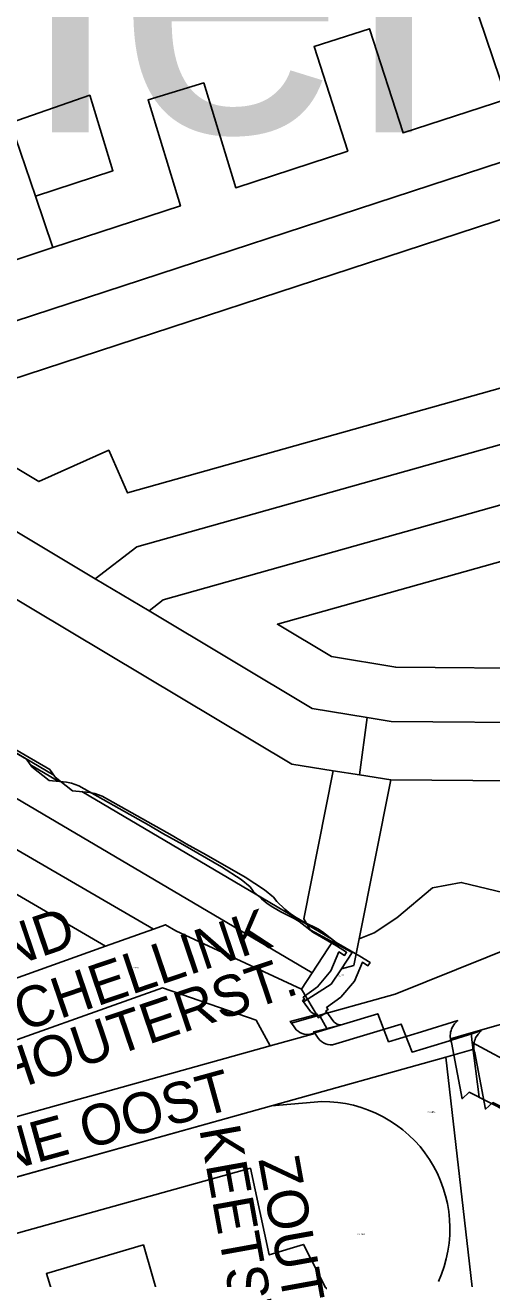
# Model space of a CAD drawing. Extents: x 14356 to 207184, y 3423 to 537581.
# Drawn here: x 133359.6 to 133479.8, y 517028.5 to 517351.4 of the extents above; entities that cross this region are included whole.
import ezdxf

# ---------------------------------------------------------------- set-up
doc = ezdxf.new("R2010")
doc.units = 0
for name, color, linetype in [('(THEMA) WIJK (VLAK)', 7, 'Continuous'), ('FRANK', 7, 'Continuous'), ('GEOCAD IKB VLAK TEKST CLASSIFICATIE', 7, 'Continuous'), ('KADER-35', 7, 'Continuous'), ('PLATTEGROND ACHTERGROND BEBOUW', 7, 'Continuous'), ('PLATTEGROND BEBOUWING', 7, 'Continuous'), ('PLATTEGROND ERFTOEGANGSWEG', 7, 'Continuous'), ('PLATTEGROND GEB ONTSL WEG C', 7, 'Continuous'), ('PLATTEGROND GEB ONTSL WEG E', 7, 'Continuous'), ('PLATTEGROND HULPLIJN', 7, 'Continuous'), ('PLATTEGROND LIJN', 7, 'Continuous'), ('PLATTEGROND NAAM ERFTOEGANGSWEG', 7, 'Continuous'), ('PLATTEGROND NAAM GEB ONTSL WEG E', 7, 'Continuous'), ('PLATTEGROND OPENBAAR GROEN', 7, 'Continuous'), ('PLATTEGROND VOET FIETSPAD', 7, 'Continuous'), ('PLATTEGROND WATER', 7, 'Continuous')]:
    doc.layers.add(name, color=color, linetype=linetype)

msp = doc.modelspace()

# ---------------------------------------------------------------- linework, layer by layer
at = {"layer": '(THEMA) WIJK (VLAK)'}
for points in [[(133337.82, 517175.95), (133365.97, 517159.67), (133367.32, 517157.73), (133371.82, 517154.22), (133376.25, 517153.77), (133377.53, 517153.49), (133379.43, 517152.79), (133397.48, 517142.72), (133401.09, 517140.55), (133406.25, 517137.72), (133416.24, 517131.99), (133421.27, 517128.71), (133423.58, 517126.79), (133424.37, 517125.68), (133426.47, 517123.67), (133427.95, 517122.53), (133429.4, 517121.57), (133431.48, 517120.36), (133434.95, 517118.64), (133436.19, 517117.86), (133439.68, 517115.14), (133445.81, 517111.59), (133448.42, 517109.97), (133447.88, 517109.15), (133446.44, 517110.05), (133444.37, 517105.21), (133440.89, 517101.01), (133437.24, 517098.35), (133437.59, 517097.87), (133437.07, 517097.51), (133439.13, 517094.69)], [(133439.13, 517094.69), (133437.07, 517097.51), (133437.59, 517097.87), (133437.24, 517098.35), (133440.89, 517101.01), (133444.37, 517105.21), (133446.44, 517110.05), (133447.88, 517109.15), (133448.42, 517109.97), (133445.81, 517111.59), (133439.68, 517115.14), (133436.19, 517117.86), (133434.95, 517118.64), (133431.48, 517120.36), (133429.4, 517121.57), (133427.95, 517122.53), (133426.47, 517123.67), (133424.37, 517125.68), (133423.58, 517126.79), (133421.27, 517128.71), (133416.24, 517131.99), (133406.25, 517137.72), (133401.09, 517140.55), (133397.48, 517142.72), (133379.43, 517152.79), (133377.53, 517153.49), (133376.25, 517153.77), (133371.82, 517154.22), (133367.32, 517157.73), (133365.97, 517159.67), (133337.82, 517175.95)], [(133441.02, 517093.96), (133433.9, 517092.15), (133434.71, 517090.97)], [(133434.71, 517090.97), (133433.9, 517092.15), (133441.02, 517093.96)], [(133438.73, 517088.76), (133456.45, 517094.12), (133459.22, 517086.92), (133467.73, 517089.45), (133477.02, 517092.34), (133476.22, 517091.5), (133475.6, 517090.54)], [(133475.6, 517090.54), (133476.22, 517091.5), (133477.02, 517092.34), (133467.73, 517089.45), (133459.22, 517086.92), (133456.45, 517094.12), (133438.73, 517088.76)], [(133475.18, 517087.35), (133475.4, 517086.67), (133478.13, 517072.21), (133479.99, 517073.92), (133494.79, 517066.39), (133507.34, 517060.27), (133512.87, 517057.42), (133608.91, 517004.69)], [(133608.91, 517004.69), (133512.87, 517057.42), (133507.34, 517060.27), (133494.79, 517066.39), (133479.99, 517073.92), (133478.13, 517072.21), (133475.4, 517086.67), (133475.18, 517087.35)]]:
    msp.add_lwpolyline(points, dxfattribs=at)
for centre, radius, start, end in [((133440.66, 517095.86), 1.93, 217.3612, 280.6329), ((133440.66, 517095.86), 1.93, 217.3612, 280.6329), ((133438.52, 517093.13), 4.37, 209.5213, 272.7871), ((133438.52, 517093.13), 4.37, 209.5213, 272.7871), ((133480.3, 517088.31), 5.2, 154.5796, 190.5868), ((133480.3, 517088.31), 5.2, 154.5796, 190.5868)]:
    msp.add_arc(centre, radius, start, end, dxfattribs=at)
at = {"layer": 'FRANK'}
for points in [[(133337.82, 517175.95), (133365.97, 517159.67), (133367.32, 517157.73), (133371.82, 517154.22), (133376.25, 517153.77), (133377.53, 517153.49), (133379.43, 517152.79), (133397.48, 517142.72), (133401.09, 517140.55), (133406.25, 517137.72), (133416.24, 517131.99), (133421.27, 517128.71), (133423.58, 517126.79), (133424.37, 517125.68), (133426.47, 517123.67), (133427.95, 517122.53), (133429.4, 517121.57), (133431.48, 517120.36), (133434.95, 517118.64), (133436.19, 517117.86), (133439.68, 517115.14), (133445.81, 517111.59), (133448.42, 517109.97), (133447.88, 517109.15), (133446.44, 517110.05), (133444.37, 517105.21), (133440.89, 517101.01), (133437.24, 517098.35), (133437.59, 517097.87), (133437.07, 517097.51), (133439.13, 517094.69)], [(133441.02, 517093.96), (133433.9, 517092.15), (133434.71, 517090.97)], [(133438.73, 517088.76), (133456.45, 517094.12), (133459.22, 517086.92), (133467.73, 517089.45), (133477.02, 517092.34), (133476.22, 517091.5), (133475.6, 517090.54)], [(133475.18, 517087.35), (133475.4, 517086.67), (133478.13, 517072.21), (133479.99, 517073.92), (133494.79, 517066.39), (133507.34, 517060.27), (133512.87, 517057.42), (133608.91, 517004.69)]]:
    msp.add_lwpolyline(points, dxfattribs=at)
for centre, radius, start, end in [((133440.66, 517095.86), 1.93, 217.3612, 280.6329), ((133438.52, 517093.13), 4.37, 209.5213, 272.7871), ((133480.3, 517088.31), 5.2, 154.5796, 190.5868)]:
    msp.add_arc(centre, radius, start, end, dxfattribs=at)
at = {"layer": 'KADER-35'}
for points in [[(133433.09, 517097.35), (133431.04, 517100.18), (133431.55, 517100.53), (133431.21, 517101.01), (133434.86, 517103.67), (133438.34, 517107.87), (133440.41, 517112.71), (133441.85, 517111.81), (133442.39, 517112.63), (133439.78, 517114.26), (133433.65, 517117.81), (133430.16, 517120.52), (133428.91, 517121.3), (133425.44, 517123.03), (133423.37, 517124.23), (133421.92, 517125.19), (133420.44, 517126.34), (133418.34, 517128.34), (133417.55, 517129.45), (133415.24, 517131.37), (133410.2, 517134.65), (133400.22, 517140.38), (133395.06, 517143.21), (133391.44, 517145.38), (133373.39, 517155.45), (133371.5, 517156.15), (133370.22, 517156.43), (133365.79, 517156.88), (133361.29, 517160.39), (133359.93, 517162.34), (133331.78, 517178.61)], [(133428.68, 517093.64), (133427.87, 517094.82), (133434.99, 517096.63)], [(133469.57, 517093.2), (133470.18, 517094.16), (133470.99, 517095), (133461.69, 517092.11), (133453.19, 517089.58), (133450.41, 517096.79), (133432.7, 517091.42)], [(133602.88, 517007.36), (133506.84, 517060.08), (133501.31, 517062.93), (133488.76, 517069.05), (133473.96, 517076.58), (133472.1, 517074.87), (133469.37, 517089.33), (133469.15, 517090.01)]]:
    msp.add_lwpolyline(points, dxfattribs=at)
for centre, radius, start, end in [((133434.63, 517098.52), 1.93, 217.3612, 280.6329), ((133432.48, 517095.79), 4.37, 209.5213, 272.7871), ((133474.26, 517090.97), 5.2, 154.5796, 190.5868)]:
    msp.add_arc(centre, radius, start, end, dxfattribs=at)
at = {"layer": 'PLATTEGROND ACHTERGROND BEBOUW'}
msp.add_line((133362.23, 517307.34), (133355.82, 517326.25), dxfattribs=at)
for points in [[(133355.82, 517326.25), (133376.25, 517333.3), (133382.18, 517313.87), (133362.23, 517307.34)], [(133499.9, 517289.83), (133486.63, 517285.39), (133495.01, 517261.55), (133385.99, 517230.9), (133381.14, 517241.88), (133363.11, 517233.84), (133332.24, 517252.3), (133494.45, 517305.34)], [(133533.47, 517194.41), (133522.02, 517191.14), (133495.48, 517185.71), (133455.02, 517186.02), (133438.47, 517188.78), (133424.58, 517197.08), (133509.31, 517220.91), (133516.02, 517201.81), (133529.31, 517206.23)], [(133346.62, 517002.28), (133335.32, 517034.07), (133417.59, 517056.98), (133422.45, 517034.68), (133431.24, 517037.38), (133436.97, 517026.27), (133444.97, 517019.88), (133449.99, 517019.42), (133450.34, 517011.6)], [(133397.06, 517013.08), (133390.07, 517037.24), (133365.06, 517029.88), (133371.9, 517007.7)]]:
    msp.add_lwpolyline(points, dxfattribs=at)
at = {"layer": 'PLATTEGROND BEBOUWING'}
for p, q in [((133463.57, 517391.43), (133483.63, 517332.32)), ((133298.68, 517256.05), (133489.8, 517318.55)), ((133366.72, 517294.08), (133362.23, 517307.34)), ((133377.67, 517208.82), (133298.68, 517256.05)), ((133432.94, 517118.36), (133432.96, 517118.39)), ((133433.53, 517107.34), (133438.97, 517115.7)), ((133430.8, 517103.14), (133433.53, 517107.34)), ((133437.32, 517097.16), (133435.61, 517096.07)), ((133422.66, 517088.5), (133310.74, 517057.32)), ((133317.11, 517043.53), (133423.04, 517073.03))]:
    msp.add_line(p, q, dxfattribs=at)
for points in [[(133483.63, 517332.32), (133456.94, 517323.59), (133448.26, 517350.45), (133433.99, 517345.84), (133442.68, 517318.92), (133413.84, 517309.49), (133405.6, 517336.49), (133391.25, 517332.11), (133399.58, 517304.83), (133366.72, 517294.08)], [(133362.23, 517307.34), (133382.18, 517313.87), (133376.25, 517333.3), (133355.82, 517326.25)], [(133494.45, 517305.34), (133332.24, 517252.3), (133363.11, 517233.84), (133381.14, 517241.88), (133385.99, 517230.9), (133495.01, 517261.55), (133486.63, 517285.39), (133499.9, 517289.83)], [(133513.17, 517252.12), (133388.34, 517217.02), (133377.67, 517208.82)], [(133391.51, 517200.54), (133395.18, 517203.36), (133518.16, 517237.94)], [(133529.31, 517206.23), (133516.02, 517201.81), (133509.31, 517220.91), (133424.58, 517197.08), (133438.47, 517188.78), (133455.02, 517186.02), (133495.48, 517185.71), (133522.02, 517191.14), (133533.47, 517194.41)], [(133447.69, 517173.05), (133433.55, 517175.41), (133391.51, 517200.54)], [(133538.12, 517181.18), (133525.36, 517177.53), (133496.85, 517171.7), (133453.81, 517172.03), (133447.69, 517173.05)], [(133265.86, 517119.46), (133341.04, 517136.98), (133380.33, 517114.2)], [(133432.96, 517118.39), (133443.78, 517112.54), (133441.03, 517108.34)], [(133380.33, 517114.2), (133338.81, 517099.37), (133343.85, 517085.24), (133394.94, 517103.49), (133419.05, 517095.1), (133422.66, 517088.5)], [(133441.03, 517108.34), (133438.44, 517104.41), (133431.29, 517099.82)], [(133435.61, 517096.07), (133435.11, 517095.74), (133430.8, 517103.14)], [(133423.04, 517073.03), (133435.98, 517074.16), (133438.03, 517074.11), (133440.08, 517073.94), (133442.11, 517073.64), (133444.12, 517073.21), (133446.1, 517072.66), (133448.04, 517071.98), (133449.93, 517071.18), (133451.77, 517070.26), (133453.54, 517069.24), (133455.25, 517068.1), (133456.89, 517066.85), (133458.44, 517065.51), (133459.91, 517064.07), (133461.28, 517062.55), (133462.55, 517060.93), (133463.73, 517059.25), (133464.79, 517057.49), (133465.74, 517055.67), (133466.57, 517053.79), (133467.28, 517051.87), (133467.88, 517049.9), (133468.34, 517047.9), (133468.68, 517045.87), (133468.9, 517043.83), (133468.98, 517041.78), (133468.93, 517039.73), (133468.76, 517037.68), (133468.46, 517035.65), (133468.03, 517033.64), (133467.48, 517031.66), (133466.8, 517029.72), (133466, 517027.83)], [(133450.34, 517011.6), (133449.99, 517019.42), (133444.97, 517019.88), (133436.97, 517026.27), (133431.24, 517037.38), (133422.45, 517034.68), (133417.59, 517056.98), (133335.32, 517034.07), (133346.62, 517002.28)], [(133371.9, 517007.7), (133365.06, 517029.88), (133390.07, 517037.24), (133397.06, 517013.08)]]:
    msp.add_lwpolyline(points, dxfattribs=at)
at = {"layer": 'PLATTEGROND ERFTOEGANGSWEG'}
for p, q in [((133483.63, 517332.32), (133463.57, 517391.43)), ((133355.82, 517326.25), (133362.23, 517307.34)), ((133489.8, 517318.55), (133298.68, 517256.05)), ((133362.23, 517307.34), (133366.72, 517294.08)), ((133352.46, 517289.42), (133366.72, 517294.08)), ((133366.72, 517294.08), (133352.46, 517289.42)), ((133391.51, 517200.54), (133377.67, 517208.82)), ((133380.33, 517114.2), (133392.66, 517118.6)), ((133431.46, 517095.29), (133428.17, 517094.38)), ((133431.25, 517095.68), (133431.46, 517095.29)), ((133435.61, 517096.07), (133437.28, 517093.01)), ((133434.2, 517091.71), (133422.66, 517088.5)), ((133469.11, 517090.31), (133474.42, 517091.84)), ((133474.42, 517091.84), (133474.73, 517089.41)), ((133467.89, 517085.56), (133475.14, 517087.65)), ((133476.54, 517075.27), (133474.73, 517089.41)), ((133474.73, 517089.41), (133512.31, 517068.89)), ((133474.73, 517089.41), (133476.54, 517075.27)), ((133475.96, 517015.81), (133467.89, 517085.56))]:
    msp.add_line(p, q, dxfattribs=at)
for points in [[(133366.72, 517294.08), (133399.58, 517304.83), (133391.25, 517332.11), (133405.6, 517336.49), (133413.84, 517309.49), (133442.68, 517318.92), (133433.99, 517345.84), (133448.26, 517350.45), (133456.94, 517323.59), (133483.63, 517332.32)], [(133377.67, 517208.82), (133388.34, 517217.02), (133513.17, 517252.12)], [(133518.16, 517237.94), (133395.18, 517203.36), (133391.51, 517200.54)], [(133392.66, 517118.6), (133395.74, 517119.7), (133398.38, 517118.17), (133430.8, 517103.14)], [(133422.66, 517088.5), (133419.05, 517095.1), (133394.94, 517103.49), (133343.85, 517085.24), (133338.81, 517099.37), (133380.33, 517114.2)], [(133430.8, 517103.14), (133435.11, 517095.74), (133435.61, 517096.07)]]:
    msp.add_lwpolyline(points, dxfattribs=at)
at = {"layer": 'PLATTEGROND GEB ONTSL WEG C'}
for p, q in [((133298.68, 517256.05), (133377.67, 517208.82)), ((133377.67, 517208.82), (133391.51, 517200.54)), ((133447.69, 517173.05), (133445.7, 517158.27)), ((133445.7, 517158.27), (133447.69, 517173.05)), ((133445.7, 517158.27), (133438.94, 517159.3)), ((133453.78, 517157.03), (133445.7, 517158.27)), ((133485.46, 517156.79), (133453.78, 517157.03))]:
    msp.add_line(p, q, dxfattribs=at)
for points in [[(133438.94, 517159.3), (133428.29, 517161.08), (133170.78, 517315.04), (133147.96, 517361.08)], [(133391.51, 517200.54), (133433.55, 517175.41), (133447.69, 517173.05)], [(133447.69, 517173.05), (133453.81, 517172.03), (133496.85, 517171.7), (133525.36, 517177.53), (133538.12, 517181.18)]]:
    msp.add_lwpolyline(points, dxfattribs=at)
at = {"layer": 'PLATTEGROND GEB ONTSL WEG E'}
for p, q in [((133428.17, 517094.38), (133431.46, 517095.29)), ((133422.66, 517088.5), (133434.2, 517091.71)), ((133474.42, 517091.84), (133469.11, 517090.31)), ((133310.74, 517057.32), (133422.66, 517088.5)), ((133475.14, 517087.65), (133467.89, 517085.56)), ((133467.89, 517085.56), (133423.04, 517073.03)), ((133423.04, 517073.03), (133317.11, 517043.53))]:
    msp.add_line(p, q, dxfattribs=at)
for points in [[(133431.46, 517095.29), (133454.9, 517101.82), (133486.43, 517114.52)], [(133494.57, 517098.24), (133488.96, 517096.02), (133474.42, 517091.84)]]:
    msp.add_lwpolyline(points, dxfattribs=at)
at = {"layer": 'PLATTEGROND HULPLIJN'}
for p, q in [((133366.72, 517294.08), (133352.46, 517289.42)), ((133377.67, 517208.82), (133391.51, 517200.54)), ((133445.7, 517158.27), (133447.69, 517173.05)), ((133445.7, 517158.27), (133438.94, 517159.3)), ((133453.78, 517157.03), (133445.7, 517158.27)), ((133380.33, 517114.2), (133392.66, 517118.6)), ((133428.17, 517094.38), (133431.46, 517095.29)), ((133422.66, 517088.5), (133434.2, 517091.71)), ((133469.11, 517090.31), (133474.42, 517091.84)), ((133467.89, 517085.56), (133475.14, 517087.65)), ((133476.54, 517075.27), (133474.73, 517089.41))]:
    msp.add_line(p, q, dxfattribs=at)
at = {"layer": 'PLATTEGROND LIJN'}
for p, q in [((133483.63, 517332.32), (133463.57, 517391.43)), ((133355.82, 517326.25), (133362.23, 517307.34)), ((133489.8, 517318.55), (133298.68, 517256.05)), ((133362.23, 517307.34), (133366.72, 517294.08)), ((133298.68, 517256.05), (133377.67, 517208.82)), ((133433.53, 517107.34), (133212.4, 517237.59)), ((133366.99, 517158.21), (133278.56, 517210.38)), ((133368.13, 517156.64), (133360.95, 517160.87)), ((133445.59, 517116.1), (133453.78, 517157.03)), ((133453.78, 517157.03), (133485.46, 517156.79)), ((133438.74, 517115.88), (133374.16, 517153.98)), ((133432.96, 517118.39), (133432.71, 517118.54)), ((133432.96, 517118.39), (133432.94, 517118.36)), ((133438.97, 517115.7), (133433.53, 517107.34)), ((133433.53, 517107.34), (133430.8, 517103.14)), ((133435.61, 517096.07), (133437.32, 517097.16)), ((133431.46, 517095.29), (133431.25, 517095.68)), ((133437.28, 517093.01), (133435.61, 517096.07)), ((133474.73, 517089.41), (133474.42, 517091.84)), ((133310.74, 517057.32), (133422.66, 517088.5)), ((133512.31, 517068.89), (133474.73, 517089.41)), ((133467.89, 517085.56), (133423.04, 517073.03)), ((133467.89, 517085.56), (133475.96, 517015.81)), ((133423.04, 517073.03), (133317.11, 517043.53))]:
    msp.add_line(p, q, dxfattribs=at)
for points in [[(133438.94, 517159.3), (133428.29, 517161.08), (133170.78, 517315.04), (133147.96, 517361.08)], [(133366.72, 517294.08), (133399.58, 517304.83), (133391.25, 517332.11), (133405.6, 517336.49), (133413.84, 517309.49), (133442.68, 517318.92), (133433.99, 517345.84), (133448.26, 517350.45), (133456.94, 517323.59), (133483.63, 517332.32)], [(133355.82, 517326.25), (133376.25, 517333.3), (133382.18, 517313.87), (133362.23, 517307.34)], [(133494.45, 517305.34), (133332.24, 517252.3), (133363.11, 517233.84), (133381.14, 517241.88), (133385.99, 517230.9), (133495.01, 517261.55), (133486.63, 517285.39), (133499.9, 517289.83)], [(133513.17, 517252.12), (133388.34, 517217.02), (133377.67, 517208.82)], [(133212.4, 517237.59), (133209.96, 517234.94), (133244.77, 517203.54), (133326.6, 517156.92), (133392.66, 517118.6)], [(133518.16, 517237.94), (133395.18, 517203.36), (133391.51, 517200.54)], [(133529.31, 517206.23), (133516.02, 517201.81), (133509.31, 517220.91), (133424.58, 517197.08), (133438.47, 517188.78), (133455.02, 517186.02), (133495.48, 517185.71), (133522.02, 517191.14), (133533.47, 517194.41)], [(133447.69, 517173.05), (133433.55, 517175.41), (133391.51, 517200.54)], [(133538.12, 517181.18), (133525.36, 517177.53), (133496.85, 517171.7), (133453.81, 517172.03), (133447.69, 517173.05)], [(133438.94, 517159.3), (133431.32, 517121.2), (133432.96, 517118.39)], [(133485.46, 517156.79), (133499.24, 517140.85), (133501.04, 517131.51), (133492.11, 517127.45), (133487.25, 517126.92), (133471.89, 517130.6), (133464.5, 517129.2), (133455.34, 517121.47), (133449.48, 517117.64), (133445.59, 517116.1)], [(133380.33, 517114.2), (133341.04, 517136.98), (133265.86, 517119.46)], [(133392.66, 517118.6), (133395.74, 517119.7), (133398.38, 517118.17), (133430.8, 517103.14)], [(133441.03, 517108.34), (133443.78, 517112.54), (133432.96, 517118.39)], [(133445.59, 517116.1), (133444.22, 517109.23), (133441.03, 517108.34)], [(133422.66, 517088.5), (133419.05, 517095.1), (133394.94, 517103.49), (133343.85, 517085.24), (133338.81, 517099.37), (133380.33, 517114.2)], [(133486.43, 517114.52), (133454.9, 517101.82), (133431.46, 517095.29)], [(133431.29, 517099.82), (133438.44, 517104.41), (133441.03, 517108.34)], [(133430.8, 517103.14), (133435.11, 517095.74), (133435.61, 517096.07)], [(133494.57, 517098.24), (133488.96, 517096.02), (133474.42, 517091.84)], [(133423.04, 517073.03), (133435.98, 517074.16), (133438.03, 517074.11), (133440.08, 517073.94), (133442.11, 517073.64), (133444.12, 517073.21), (133446.1, 517072.66), (133448.04, 517071.98), (133449.93, 517071.18), (133451.77, 517070.26), (133453.54, 517069.24), (133455.25, 517068.1), (133456.89, 517066.85), (133458.44, 517065.51), (133459.91, 517064.07), (133461.28, 517062.55), (133462.55, 517060.93), (133463.73, 517059.25), (133464.79, 517057.49), (133465.74, 517055.67), (133466.57, 517053.79), (133467.28, 517051.87), (133467.88, 517049.9), (133468.34, 517047.9), (133468.68, 517045.87), (133468.9, 517043.83), (133468.98, 517041.78), (133468.93, 517039.73), (133468.76, 517037.68), (133468.46, 517035.65), (133468.03, 517033.64), (133467.48, 517031.66), (133466.8, 517029.72), (133466, 517027.83)], [(133450.34, 517011.6), (133449.99, 517019.42), (133444.97, 517019.88), (133436.97, 517026.27), (133431.24, 517037.38), (133422.45, 517034.68), (133417.59, 517056.98), (133335.32, 517034.07), (133346.62, 517002.28)], [(133397.06, 517013.08), (133390.07, 517037.24), (133365.06, 517029.88), (133371.9, 517007.7)]]:
    msp.add_lwpolyline(points, dxfattribs=at)
at = {"layer": 'PLATTEGROND OPENBAAR GROEN'}
for p, q in [((133212.4, 517237.59), (133433.53, 517107.34)), ((133433.53, 517107.34), (133430.8, 517103.14)), ((133435.61, 517096.07), (133437.32, 517097.16)), ((133431.46, 517095.29), (133431.25, 517095.68)), ((133437.28, 517093.01), (133435.61, 517096.07)), ((133474.73, 517089.41), (133474.42, 517091.84)), ((133512.31, 517068.89), (133474.73, 517089.41)), ((133423.04, 517073.03), (133467.89, 517085.56)), ((133467.89, 517085.56), (133475.96, 517015.81))]:
    msp.add_line(p, q, dxfattribs=at)
for points in [[(133392.66, 517118.6), (133326.6, 517156.92), (133244.77, 517203.54), (133209.96, 517234.94), (133212.4, 517237.59)], [(133445.59, 517116.1), (133449.48, 517117.64), (133455.34, 517121.47), (133464.5, 517129.2), (133471.89, 517130.6), (133487.25, 517126.92), (133492.11, 517127.45), (133501.04, 517131.51), (133499.24, 517140.85), (133485.46, 517156.79)], [(133430.8, 517103.14), (133398.38, 517118.17), (133395.74, 517119.7), (133392.66, 517118.6)], [(133441.03, 517108.34), (133444.22, 517109.23), (133445.59, 517116.1)], [(133486.43, 517114.52), (133454.9, 517101.82), (133431.46, 517095.29)], [(133431.29, 517099.82), (133438.44, 517104.41), (133441.03, 517108.34)], [(133474.42, 517091.84), (133488.96, 517096.02), (133494.57, 517098.24)], [(133466, 517027.83), (133466.8, 517029.72), (133467.48, 517031.66), (133468.03, 517033.64), (133468.46, 517035.65), (133468.76, 517037.68), (133468.93, 517039.73), (133468.98, 517041.78), (133468.9, 517043.83), (133468.68, 517045.87), (133468.34, 517047.9), (133467.88, 517049.9), (133467.28, 517051.87), (133466.57, 517053.79), (133465.74, 517055.67), (133464.79, 517057.49), (133463.73, 517059.25), (133462.55, 517060.93), (133461.28, 517062.55), (133459.91, 517064.07), (133458.44, 517065.51), (133456.89, 517066.85), (133455.25, 517068.1), (133453.54, 517069.24), (133451.77, 517070.26), (133449.93, 517071.18), (133448.04, 517071.98), (133446.1, 517072.66), (133444.12, 517073.21), (133442.11, 517073.64), (133440.08, 517073.94), (133438.03, 517074.11), (133435.98, 517074.16), (133423.04, 517073.03)]]:
    msp.add_lwpolyline(points, dxfattribs=at)
at = {"layer": 'PLATTEGROND VOET FIETSPAD'}
for p, q in [((133433.53, 517107.34), (133212.4, 517237.59)), ((133278.56, 517210.38), (133366.99, 517158.21)), ((133360.95, 517160.87), (133368.13, 517156.64)), ((133438.94, 517159.3), (133445.7, 517158.27)), ((133445.7, 517158.27), (133453.78, 517157.03)), ((133453.78, 517157.03), (133445.59, 517116.1)), ((133374.16, 517153.98), (133438.74, 517115.88)), ((133392.66, 517118.6), (133380.33, 517114.2)), ((133432.71, 517118.54), (133432.96, 517118.39)), ((133432.96, 517118.39), (133432.94, 517118.36)), ((133438.97, 517115.7), (133433.53, 517107.34))]:
    msp.add_line(p, q, dxfattribs=at)
for points in [[(133212.4, 517237.59), (133209.96, 517234.94), (133244.77, 517203.54), (133326.6, 517156.92), (133392.66, 517118.6)], [(133432.96, 517118.39), (133431.32, 517121.2), (133438.94, 517159.3)], [(133380.33, 517114.2), (133341.04, 517136.98), (133265.86, 517119.46)], [(133441.03, 517108.34), (133443.78, 517112.54), (133432.96, 517118.39)], [(133445.59, 517116.1), (133444.22, 517109.23), (133441.03, 517108.34)]]:
    msp.add_lwpolyline(points, dxfattribs=at)
at = {"layer": 'PLATTEGROND WATER'}
for p, q in [((133366.99, 517158.21), (133278.56, 517210.38)), ((133368.13, 517156.64), (133360.95, 517160.87)), ((133445.59, 517116.1), (133453.78, 517157.03)), ((133453.78, 517157.03), (133485.46, 517156.79)), ((133438.74, 517115.88), (133374.16, 517153.98)), ((133432.96, 517118.39), (133432.71, 517118.54))]:
    msp.add_line(p, q, dxfattribs=at)
for points in [[(133147.96, 517361.08), (133170.78, 517315.04), (133428.29, 517161.08), (133438.94, 517159.3)], [(133438.94, 517159.3), (133431.32, 517121.2), (133432.96, 517118.39)], [(133485.46, 517156.79), (133499.24, 517140.85), (133501.04, 517131.51), (133492.11, 517127.45), (133487.25, 517126.92), (133471.89, 517130.6), (133464.5, 517129.2), (133455.34, 517121.47), (133449.48, 517117.64), (133445.59, 517116.1)]]:
    msp.add_lwpolyline(points, dxfattribs=at)

# ---------------------------------------------------------------- texts
at = {"layer": 'GEOCAD IKB VLAK TEKST CLASSIFICATIE'}
for s, p in [('CPG_ERFW', (133386.1, 517108.46)), ('cpg_bw1', (133439.76, 517106.55)), ('cpg_grn1', (133463.23, 517071.34)), ('cpg_bw1', (133445.11, 517039.89))]:
    msp.add_text(s, height=0.35, dxfattribs=at).set_placement(p)
at = {"layer": 'PLATTEGROND LIJN'}
msp.add_text('Venenlaankwartier', height=80, dxfattribs=at).set_placement((133192.58, 517323.78))
at = {"layer": 'PLATTEGROND NAAM ERFTOEGANGSWEG'}
for s, rotation, p in [('SCHOTLAND', 18.7423, (133291.3, 517086.78)), ('SCHELLINK', 18.7423, (133350.03, 517089.12)), ('HOUTERST.', 18.7423, (133353.65, 517076)), ('KEETST.', 280.239, (133404.4, 517067.16)), ('ZOUT', 280.239, (133419.63, 517059.29))]:
    msp.add_text(s, height=10.5, rotation=rotation, dxfattribs=at).set_placement(p)
at = {"layer": 'PLATTEGROND NAAM GEB ONTSL WEG E'}
msp.add_text('KLEINE OOST', height=10.5, rotation=15.4642, dxfattribs=at).set_placement((133323.41, 517047.5))

doc.saveas('drawing.dxf')
